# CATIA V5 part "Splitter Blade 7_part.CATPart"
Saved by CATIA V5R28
Part number: Splitter Blade 7_part
Definition: design
Nomenclature: Splitter Blade 7_part
Source: Unknown
Bounding box of the stored display mesh (mm): x -8.91 to -3.255, y -2.93 to 4.878, z 4.237 to 7.742
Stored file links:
  D:\paraturbo-cad\STEP\Turbocompressor_for_Christophe\Splitter Blade 7_part.CATPart
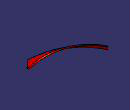
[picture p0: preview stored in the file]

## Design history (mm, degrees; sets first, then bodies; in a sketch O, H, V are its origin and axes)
Body1 "MANIFOLD_SOLID_BREP #73596" (main body)
  Solid1: solid without history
